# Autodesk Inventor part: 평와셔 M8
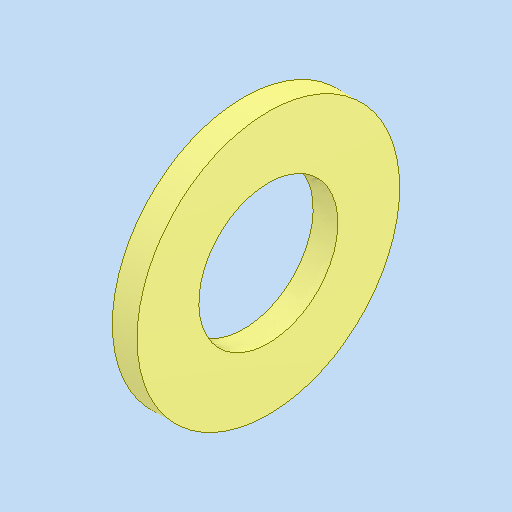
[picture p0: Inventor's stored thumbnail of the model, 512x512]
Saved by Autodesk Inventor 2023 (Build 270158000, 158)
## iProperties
Created: 2024-11
Part Number: 평와셔 M8
Material: 강철, 연강
Description: 평면 와셔
Document SubType Name: Modeling
Designer: asung
Density: 7.85 g/cm^3
Appearance: 기본값
Author: jhkim
Sending System: Autodesk Inventor 2025
Preprocessor: ST-DEVELOPER v20
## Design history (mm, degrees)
node "평와셔 M81"
node "솔리드1"
body "Solid1"
